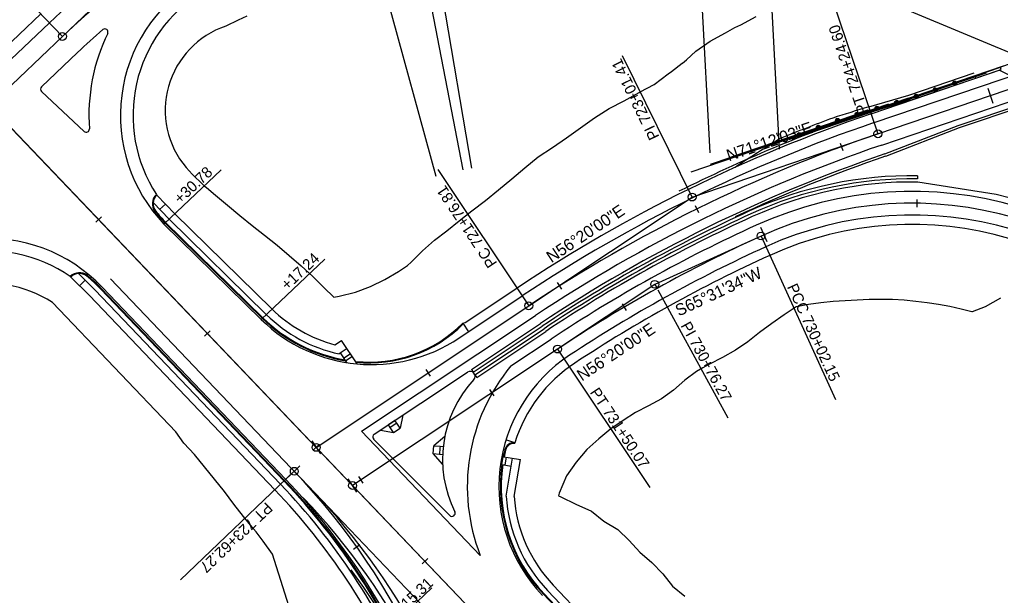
# Model space of a CAD drawing. Extents: x 1300404 to 1323571, y 237813 to 252077.
# Drawn here: x 1310171 to 1310793, y 241355 to 241720 of the extents above; entities that cross this region are included whole.
import ezdxf

# ---------------------------------------------------------------- set-up
doc = ezdxf.new("R2010")
doc.units = 0
for name, color, linetype in [('R_Barrier Wall', 7, 'Continuous'), ('R_Bridge', 7, 'Continuous'), ('R_Const Limits', 7, 'Continuous'), ('R_Curb', 7, 'Continuous'), ('R_Draft', 7, 'Continuous'), ('R_Flooplain', 7, 'Continuous'), ('R_Future', 7, 'Continuous'), ('R_Guardrail', 7, 'Continuous'), ('R_Horz Alg Annot', 7, 'Continuous'), ('R_Horz Alg Annot Leader', 7, 'Continuous'), ('R_Horz Alg Major Ticks', 7, 'Continuous'), ('R_Horz Alg Minor Ticks', 7, 'Continuous'), ('R_Horz Alg Tangents', 7, 'Continuous'), ('R_Horz Alg Tangents Text', 7, 'Continuous'), ('R_Lane Edge', 7, 'Continuous'), ('R_No Plot', 7, 'Continuous'), ('R_Proposed', 7, 'Continuous'), ('R_Shoulder', 7, 'Continuous'), ('R_Sidewalk Edge', 7, 'Continuous')]:
    doc.layers.add(name, color=color, linetype=linetype)

msp = doc.modelspace()

# ---------------------------------------------------------------- linework, layer by layer
at = {"layer": 'R_Barrier Wall'}
for p, q in [((1310740.8, 241621.29), (1310740.77, 241619.29)), ((1310458.67, 241496.57), (1310502.53, 241525.79)), ((1310459.78, 241494.91), (1310503.64, 241524.12)), ((1310459.78, 241494.91), (1310458.67, 241496.57))]:
    msp.add_line(p, q, dxfattribs=at)
for centre, radius, start, end in [((1310737.29, 241372.32), 249, 89.19241, 114.47385), ((1310737.29, 241372.32), 247, 89.19241, 114.47385), ((1311023.32, 240743.92), 939.43, 114.47385, 123.66667), ((1311023.32, 240743.92), 937.43, 114.47385, 123.66667)]:
    msp.add_arc(centre, radius, start, end, dxfattribs=at)
at = {"layer": 'R_Bridge'}
for p, q in [((1311052, 241778.36), (1310793.35, 241690.31)), ((1310777.26, 241684.81), (1310793.35, 241690.31)), ((1310777.77, 241683.31), (1310793.86, 241688.82)), ((1310824.24, 241672.75), (1310792.52, 241688.36)), ((1310793.86, 241688.82), (1310793.35, 241690.31)), ((1310777.77, 241683.31), (1310777.26, 241684.81))]:
    msp.add_line(p, q, dxfattribs=at)
at = {"layer": 'R_Const Limits'}
msp.add_line((1310191.61, 241540.77), (1310269.94, 241458.71), dxfattribs=at)
for points in [[(1310314.9, 241722.64), (1310309.35, 241720.2), (1310301.58, 241716.34)], [(1310584.48, 241687.59), (1310591.41, 241692.73), (1310591.43, 241692.75), (1310594.13, 241695.01), (1310599.9, 241700.51), (1310609.14, 241706.76), (1310618.85, 241711.98), (1310624.67, 241715.54), (1310628.59, 241717.21), (1310638.32, 241722.5)], [(1310370.08, 241544.27), (1310373.6, 241544.72), (1310383.89, 241547.31), (1310393.48, 241550.95), (1310402.48, 241555.48), (1310411.22, 241560.38), (1310416.88, 241564.18), (1310419.22, 241566.42), (1310426.5, 241573.52), (1310434.03, 241580.27), (1310441.96, 241586.4), (1310449.77, 241592.71), (1310457.88, 241598.99), (1310466.44, 241605.52), (1310474.79, 241612.43), (1310483.12, 241619.4), (1310491.51, 241626.35), (1310499.99, 241633.22), (1310509.05, 241639.14), (1310517.95, 241645.38), (1310526.77, 241651.8), (1310535.69, 241658.1), (1310544.88, 241663.94), (1310554.52, 241668.94), (1310564.05, 241674.17), (1310564.71, 241674.57), (1310573.63, 241679.31), (1310582.46, 241686.09), (1310584.48, 241687.59)], [(1310276.4, 241626.48), (1310280.14, 241622.4), (1310287.31, 241615.42), (1310287.9, 241614.9), (1310289.27, 241613.78), (1310295.05, 241608.98), (1310302.77, 241602.52), (1310310.57, 241596.14), (1310318.39, 241589.78), (1310326.25, 241583.46), (1310334.12, 241577.15), (1310341.84, 241570.69), (1310349.39, 241564.08), (1310356.82, 241557.34), (1310363.87, 241550.24), (1310370.08, 241544.27)], [(1310793.35, 241543.52), (1310783.74, 241538.05), (1310775.34, 241534.81), (1310775.3, 241534.82), (1310768.35, 241536.63), (1310761.29, 241538.23), (1310754.15, 241539.61), (1310746.93, 241540.56), (1310739.67, 241541.4), (1310732.34, 241542.17), (1310724.95, 241542.66), (1310717.52, 241542.73), (1310710.03, 241542.64), (1310702.49, 241542.33), (1310694.86, 241541.94), (1310687.16, 241541.37), (1310679.38, 241540.57), (1310671.54, 241539.5), (1310663.69, 241538.06), (1310663.69, 241538.06), (1310655.99, 241533.02), (1310648.19, 241527.46), (1310640.52, 241521.69), (1310632.95, 241515.83), (1310625.11, 241510.58), (1310616.97, 241505.92), (1310608.62, 241501.68), (1310604.51, 241499.3), (1310600.51, 241496.99), (1310592.94, 241491.35), (1310585.75, 241485.13), (1310578.22, 241479.54), (1310570, 241475.1), (1310561.6, 241470.92), (1310553.78, 241465.81), (1310546.04, 241460.59), (1310545.98, 241460.55), (1310538.33, 241454.13), (1310530.82, 241447.37), (1310524.1, 241439.42), (1310517.88, 241430.71), (1310513.23, 241419.66), (1310512.73, 241417.99)], [(1310353.4, 241310.55), (1310353.4, 241310.55), (1310353.4, 241310.55), (1310353.4, 241310.55), (1310331.28, 241380.9), (1310331.28, 241380.9), (1310331.28, 241380.9), (1310331.28, 241380.9), (1310331.28, 241380.9), (1310331.28, 241380.9), (1310325.41, 241389.12), (1310320.8, 241395.02), (1310319.2, 241397.02), (1310312.88, 241404.81), (1310306.59, 241412.63), (1310300.69, 241420.82), (1310294.4, 241428.64), (1310288.08, 241436.43), (1310281.76, 241444.22), (1310274.87, 241451.47), (1310269.94, 241458.71)], [(1310512.73, 241417.99), (1310514.22, 241417.27), (1310523.82, 241412.62), (1310533.74, 241408.26), (1310541.64, 241401.97), (1310550.52, 241396.63), (1310557.77, 241389.72), (1310564.39, 241382.22), (1310571.99, 241375.65), (1310579.02, 241368.53), (1310585.25, 241360.65), (1310592.98, 241354.21)]]:
    msp.add_lwpolyline(points, dxfattribs=at)
for centre, radius, start, end in [((1310319.65, 241662.82), 56.49, 108.65527, 220.03677), ((1310151.28, 241478.79), 73.94, 56.94848, 152.94523)]:
    msp.add_arc(centre, radius, start, end, dxfattribs=at)
at = {"layer": 'R_Curb'}
for p, q in [((1310324.82, 241530.66), (1310263.03, 241591.22)), ((1310325.17, 241531.02), (1310263.38, 241591.57)), ((1310221.96, 241549.52), (1310338.56, 241427.37)), ((1310222.32, 241549.87), (1310338.92, 241427.71)), ((1310503.65, 241355.78), (1310622.61, 241231.16)), ((1310503.29, 241355.44), (1310622.23, 241230.84))]:
    msp.add_line(p, q, dxfattribs=at)
for centre, radius, start, end in [((1310262.92, 241603.57), 8, 132.64931, 217.96091), ((1310262.92, 241603.57), 7.5, 133.28925, 217.96091), ((1310334.67, 241659.55), 99, 217.96123, 223.66667), ((1310334.67, 241659.55), 98.5, 217.96123, 223.66667), ((1310208.6, 241551.72), 8, 50.49362, 135.80556), ((1310208.6, 241551.72), 7.5, 50.49362, 135.80556), ((1310150.71, 241481.51), 98.5, 43.66667, 50.49362), ((1310150.71, 241481.51), 99, 43.66667, 50.49362), ((1310394.12, 241601.36), 99, 225.57582, 260.49906), ((1310394.12, 241601.36), 98.5, 225.57582, 260.22564), ((1310392.66, 241586.67), 83.73, 264.06748, 315.12019), ((1310392.66, 241586.67), 84.23, 264.34826, 315.05129), ((1310484.54, 241445.76), 6, 84.11696, 166.34051), ((1310484.54, 241445.76), 5.5, 85.15463, 166.3405), ((1310574.91, 241423.8), 99, 166.34071, 168.90949), ((1310574.91, 241423.8), 98.5, 166.34071, 168.90215), ((1310574.91, 241423.8), 99, 171.80353, 223.66667), ((1310574.91, 241423.8), 98.5, 171.81087, 223.66667), ((1310032.27, 241135.01), 423.42, 22.2443, 43.66667), ((1310032.27, 241135.01), 423.92, 21.97246, 43.66667)]:
    msp.add_arc(centre, radius, start, end, dxfattribs=at)
at = {"layer": 'R_Draft'}
for centre, start, end in [((1310334.67, 241659.55), 121.63465, 223.66667), ((1310150.71, 241481.51), 43.66667, 147.10039)]:
    msp.add_arc(centre, 100, start, end, dxfattribs=at)
at = {"layer": 'R_Flooplain'}
msp.add_lwpolyline([(1309009.78, 242685.04), (1309044.07, 242596.21), (1309055.9, 242542.38), (1309352.07, 242367.77), (1309503.16, 242292.41), (1309669.46, 242230.8), (1309815.49, 242150.85), (1309936.66, 242057.64), (1310419.39, 241839.75), (1310733.16, 241727.16), (1311043.67, 241597.79), (1311103.17, 241577.86), (1311152.77, 241553.58), (1311178, 241525.7), (1311328.48, 241486.66), (1311553.07, 241380.98), (1311870.34, 241289.99), (1312137.52, 241213.62)], dxfattribs=at)
at = {"layer": 'R_Future'}
msp.add_line((1310228.47, 241555.74), (1310356.22, 241421.9), dxfattribs=at)
for radius, end in [(432.42, 43.66667), (424.92, 43.66667), (418.92, 36.25513)]:
    msp.add_arc((1310043.42, 241123.33), radius, 336.82333, end, dxfattribs=at)
at = {"layer": 'R_Guardrail'}
for p, q in [((1310695.74, 241656.55), (1310784.48, 241686.76)), ((1310795.06, 241690.87), (1310710.74, 241662.17)), ((1310683.4, 241652.3), (1310772.14, 241682.51)), ((1310736.34, 241669.24), (1310777.76, 241683.34)), ((1310765.05, 241679.12), (1310763.06, 241680.05)), ((1310659, 241644.31), (1310747.75, 241674.52)), ((1310671.39, 241648.23), (1310760.13, 241678.44)), ((1310752.71, 241674.86), (1310750.72, 241675.79)), ((1310633.75, 241636.67), (1310722.5, 241666.88)), ((1310646.47, 241640.5), (1310735.21, 241670.71)), ((1310736.34, 241669.24), (1310688.1, 241654.62)), ((1310728.31, 241666.87), (1310726.33, 241667.8)), ((1310740.7, 241670.8), (1310738.71, 241671.73)), ((1310827.89, 241672.29), (1310767.18, 241651.63)), ((1310621.4, 241632.92), (1310710.15, 241663.13)), ((1310715.78, 241663.07), (1310713.79, 241664)), ((1310609.24, 241628.56), (1310697.99, 241658.77)), ((1310690.71, 241655.48), (1310688.73, 241656.41)), ((1310703.06, 241659.24), (1310701.08, 241660.17)), ((1310597.12, 241623.81), (1310685.87, 241654.02)), ((1310678.55, 241651.12), (1310676.57, 241652.05)), ((1310767.18, 241651.63), (1310720.49, 241633.62)), ((1310666.43, 241646.37), (1310664.45, 241647.3))]:
    msp.add_line(p, q, dxfattribs=at)
for points in [[(1310765.39, 241679.51), (1310763.15, 241680.55)], [(1310764.35, 241678.86), (1310763.32, 241679.34)], [(1310765.53, 241679.98), (1310763.42, 241680.97)], [(1310765.49, 241680.55), (1310763.88, 241681.3)], [(1310753.05, 241675.25), (1310750.81, 241676.3)], [(1310752.01, 241674.61), (1310750.98, 241675.09)], [(1310753.19, 241675.73), (1310751.08, 241676.72)], [(1310753.15, 241676.3), (1310751.55, 241677.05)], [(1310728.65, 241667.26), (1310726.41, 241668.31)], [(1310727.61, 241666.61), (1310726.58, 241667.09)], [(1310728.8, 241667.74), (1310726.68, 241668.73)], [(1310728.75, 241668.31), (1310727.15, 241669.06)], [(1310741.04, 241671.19), (1310738.79, 241672.24)], [(1310739.99, 241670.54), (1310738.97, 241671.02)], [(1310741.18, 241671.67), (1310739.07, 241672.65)], [(1310741.14, 241672.23), (1310739.53, 241672.98)], [(1310703.4, 241659.63), (1310701.16, 241660.67)], [(1310703.55, 241660.1), (1310701.43, 241661.09)], [(1310703.5, 241660.67), (1310701.9, 241661.42)], [(1310716.12, 241663.46), (1310713.88, 241664.5)], [(1310715.08, 241662.81), (1310714.05, 241663.29)], [(1310716.26, 241663.93), (1310714.15, 241664.92)], [(1310716.22, 241664.5), (1310714.62, 241665.25)], [(1310691.05, 241655.87), (1310688.81, 241656.92)], [(1310690.01, 241655.23), (1310688.98, 241655.71)], [(1310691.2, 241656.35), (1310689.08, 241657.34)], [(1310691.15, 241656.92), (1310689.55, 241657.67)], [(1310702.36, 241658.98), (1310701.34, 241659.46)], [(1310666.92, 241647.24), (1310664.8, 241648.22)], [(1310666.87, 241647.8), (1310665.27, 241648.55)], [(1310678.89, 241651.51), (1310676.65, 241652.56)], [(1310677.85, 241650.86), (1310676.82, 241651.34)], [(1310679.04, 241651.99), (1310676.92, 241652.98)], [(1310678.99, 241652.56), (1310677.39, 241653.31)], [(1310666.77, 241646.76), (1310664.53, 241647.81)], [(1310665.73, 241646.11), (1310664.7, 241646.59)]]:
    msp.add_lwpolyline(points, dxfattribs=at)
for centre in [(1310764.31, 241680.13), (1310739.96, 241671.81), (1310751.97, 241675.87), (1310727.58, 241667.88), (1310702.33, 241660.25), (1310715.04, 241664.08), (1310689.98, 241656.49), (1310665.7, 241647.38), (1310677.81, 241652.13)]:
    msp.add_circle(centre, 1.25, dxfattribs=at)
for centre, radius, start, end in [((1311023.32, 240743.9), 970.01, 108.79905, 116.57911), ((1311023.32, 240743.92), 970.43, 110.20788, 111.71745), ((1311023.33, 240743.9), 939.85, 108.79713, 115.07369)]:
    msp.add_arc(centre, radius, start, end, dxfattribs=at)
at = {"layer": 'R_Horz Alg Annot'}
for p, q in [((1310262.33, 241590.5), (1310298.54, 241625.06)), ((1310324.12, 241529.95), (1310364.42, 241568.41))]:
    msp.add_line(p, q, dxfattribs=at)
at = {"layer": 'R_Horz Alg Annot Leader'}
msp.add_line((1310418.29, 241346.01), (1310432.36, 241359.45), dxfattribs=at)
for points in [[(1310197.87, 241709.76), (1310171.2, 241737.69)], [(1310687.13, 241731.51), (1310715.59, 241647.91)], [(1310597.64, 241607.76), (1310553.44, 241697.46)], [(1310436.23, 241625.33), (1310493.94, 241538.69)], [(1310641.38, 241583.02), (1310688.62, 241479.23)], [(1310573.92, 241552.31), (1310574.92, 241550.49)], [(1310575.79, 241548.91), (1310620.4, 241467.47)], [(1310512.23, 241511.22), (1310570.82, 241423.27)], [(1310345.07, 241433.58), (1310272.73, 241364.53)]]:
    msp.add_lwpolyline(points, dxfattribs=at)
at = {"layer": 'R_Horz Alg Major Ticks'}
for points in [[(1310785.35, 241676.94), (1310788.57, 241667.47)], [(1310645.37, 241579.33), (1310641.31, 241588.47)], [(1310356.15, 241452.92), (1310361.7, 241444.6)], [(1310356.15, 241452.92), (1310361.7, 241444.6)], [(1310341.45, 241430.13), (1310348.69, 241437.03)], [(1310384.83, 241420.36), (1310379.29, 241428.68)]]:
    msp.add_lwpolyline(points, dxfattribs=at)
at = {"layer": 'R_Horz Alg Minor Ticks'}
for points in [[(1310691.53, 241642.03), (1310693.26, 241637.34)], [(1310740.51, 241601.3), (1310740.58, 241606.3)], [(1310599.47, 241602.43), (1310601.68, 241597.94)], [(1310222.64, 241595.16), (1310219.02, 241591.71)], [(1310512.05, 241553.42), (1310514.72, 241549.19)], [(1310555.91, 241535.68), (1310553.37, 241539.99)], [(1310291.69, 241522.82), (1310288.07, 241519.37)], [(1310428.62, 241498.19), (1310431.39, 241494.02)], [(1310472.06, 241481.46), (1310469.29, 241485.62)], [(1310360.73, 241450.48), (1310357.11, 241447.03)], [(1310388.83, 241426.03), (1310386.06, 241430.19)], [(1310382.64, 241384.15), (1310386.72, 241387.05)], [(1310429.78, 241378.15), (1310426.16, 241374.69)]]:
    msp.add_lwpolyline(points, dxfattribs=at)
at = {"layer": 'R_Horz Alg Tangents'}
for p, q in [((1310197.87, 241709.76), (1310313.6, 241820.22)), ((1310597.64, 241607.76), (1310715.59, 241647.91)), ((1310493.94, 241538.69), (1310597.64, 241607.76)), ((1310641.38, 241583.02), (1310573.92, 241552.31)), ((1310573.92, 241552.31), (1310512.23, 241511.22)), ((1310577.76, 241189.8), (1310345.07, 241433.58))]:
    msp.add_line(p, q, dxfattribs=at)
at = {"layer": 'R_Lane Edge'}
for p, q in [((1310713.17, 241655.01), (1311572.42, 241947.51)), ((1310718.01, 241640.81), (1311577.25, 241933.31)), ((1310165.2, 241695.16), (1310189.58, 241718.44)), ((1310184.6, 241677.73), (1310207.53, 241699.63)), ((1310211.61, 241649.44), (1310184.61, 241674.83)), ((1310257.5, 241609.46), (1310257.78, 241609.03)), ((1310324.12, 241529.95), (1310262.33, 241590.5)), ((1310203.22, 241556.95), (1310202.86, 241557.3)), ((1310223.05, 241550.56), (1310339.64, 241428.4)), ((1310449.55, 241518.14), (1310489.78, 241544.93)), ((1310387.84, 241459.01), (1310498.1, 241532.45)), ((1310452, 241527.58), (1310455.6, 241522.17)), ((1310482.64, 241500.53), (1310508.08, 241517.47)), ((1310395.77, 241457.08), (1310454.97, 241496.51)), ((1310463.13, 241380.14), (1310387.84, 241459.01)), ((1310443.76, 241405.52), (1310395.46, 241454)), ((1310485.15, 241451.73), (1310479.42, 241453.51)), ((1310485, 241451.24), (1310485.15, 241451.73))]:
    msp.add_line(p, q, dxfattribs=at)
for centre, radius, start, end in [((1310496.44, 241396.96), 444.42, 93.06037, 133.66667), ((1310334.67, 241659.55), 100, 121.63465, 223.66667), ((1310496.44, 241396.96), 418.42, 130.71608, 133.66667), ((1310334.67, 241659.55), 120, 154.23405, 184.06474), ((1310224.8, 241712.58), 2, 334.23359, 130.71634), ((1310185.98, 241676.29), 2, 133.66667, 226.76016), ((1311023.32, 240743.92), 962.43, 108.79905, 123.66667), ((1310212.98, 241650.9), 2, 226.76016, 4.06474), ((1311023.32, 240743.92), 947.43, 108.79905, 123.66667), ((1310737.29, 241372.32), 239, 311.16667, 114.47385), ((1310737.29, 241372.32), 224, 311.16667, 114.47385), ((1311023.32, 240743.92), 929.43, 114.47385, 123.66667), ((1310150.71, 241481.51), 100, 43.66667, 147.10039), ((1311023.32, 240743.92), 914.43, 114.47385, 123.40686), ((1310394.12, 241601.36), 100, 225.57582, 303.66667), ((1310574.91, 241423.8), 100, 123.40686, 223.66667), ((1310574.91, 241423.8), 120, 140.25051, 201.33502), ((1310456.7, 241493.92), 3.12, 317.4059, 123.66667), ((1310514.2, 241441.05), 75, 137.40588, 206.29937), ((1310396.88, 241455.41), 2, 123.66667, 224.88819), ((1310514.2, 241441.05), 77, 173.73262, 177.45378), ((1310032.27, 241135.01), 424.92, 327.80537, 43.66667), ((1310445.17, 241406.93), 2, 224.88819, 26.29937)]:
    msp.add_arc(centre, radius, start, end, dxfattribs=at)
at = {"layer": 'R_No Plot'}
for p, q in [((1310609.19, 241635.74), (1310598.52, 241835.45)), ((1310642.2, 241837.79), (1310652.88, 241638.07)), ((1310424.03, 241823.27), (1310457.52, 241626.09)), ((1310452.23, 241625.13), (1310414.19, 241821.48)), ((1310390.21, 241784.27), (1310434.96, 241621.1))]:
    msp.add_line(p, q, dxfattribs=at)
at = {"layer": 'R_Proposed'}
for p, q in [((1310715.59, 241647.91), (1311574.84, 241940.41)), ((1310111.34, 241627.16), (1310197.87, 241709.76)), ((1310111.34, 241627.16), (1310197.87, 241709.76)), ((1310111.34, 241627.16), (1310197.87, 241709.76)), ((1310151.78, 241665.77), (1310197.87, 241709.76)), ((1310151.78, 241665.77), (1311952.58, 239779.15)), ((1310165.59, 241651.3), (1311952.63, 239779.09)), ((1310165.59, 241651.3), (1311952.63, 239779.09)), ((1310358.92, 241448.76), (1310493.94, 241538.69)), ((1310512.23, 241511.22), (1310382.06, 241424.52))]:
    msp.add_line(p, q, dxfattribs=at)
for centre in [(1310197.87, 241709.76), (1310715.59, 241647.91), (1310597.64, 241607.76), (1310641.38, 241583.02), (1310573.92, 241552.31), (1310493.94, 241538.69), (1310512.23, 241511.22), (1310358.92, 241448.76), (1310345.07, 241433.58), (1310382.06, 241424.52)]:
    msp.add_circle(centre, 2.5, dxfattribs=at)
for centre, radius, start, end in [((1310496.44, 241396.96), 432.42, 93.06037, 133.66667), ((1311023.32, 240743.92), 954.93, 108.79906, 123.66667), ((1310737.29, 241372.32), 231.5, 311.16667, 114.47385), ((1311023.32, 240743.92), 921.93, 114.47385, 123.66667), ((1310032.27, 241135.01), 432.42, 327.80537, 43.66667), ((1310032.27, 241135.01), 432.42, 327.80537, 43.66667)]:
    msp.add_arc(centre, radius, start, end, dxfattribs=at)
at = {"layer": 'R_Shoulder'}
for p, q in [((1310766.63, 241653.14), (1311578.54, 241929.52)), ((1310137.98, 241680.24), (1310184.06, 241724.22)), ((1310711.24, 241660.69), (1310792.52, 241688.36)), ((1310735.22, 241672.55), (1310776.63, 241686.65)), ((1310709.8, 241665.01), (1310735.22, 241672.55)), ((1310719.94, 241635.13), (1310766.63, 241653.14)), ((1310790.63, 241609.39), (1310740.89, 241617.29)), ((1310453.53, 241527.99), (1310486.46, 241549.93)), ((1310452, 241527.58), (1310453.53, 241527.99)), ((1310457.56, 241498.24), (1310501.42, 241527.45)), ((1310460.89, 241493.24), (1310504.75, 241522.46)), ((1310457.56, 241498.24), (1310458.67, 241496.57)), ((1310459.78, 241494.91), (1310460.89, 241493.24))]:
    msp.add_line(p, q, dxfattribs=at)
for centre, radius, start, end in [((1310334.67, 241659.55), 92, 121.63465, 212.98944), ((1311023.32, 240743.92), 968.43, 108.79905, 123.66667), ((1310986.89, 240731.33), 973.93, 106.52925, 107.93807), ((1311023.32, 240743.92), 973.93, 110.20788, 112.30788), ((1311169.5, 240806.87), 984.13, 121.61376, 123.59375), ((1311023.32, 240743.92), 941.43, 108.79905, 123.66667), ((1310737.29, 241372.32), 245, 89.15679, 114.47385), ((1310737.29, 241372.32), 243, 311.16667, 77.31825), ((1311023.32, 240743.92), 935.43, 114.47385, 123.66667), ((1310737.29, 241372.32), 218, 311.16667, 114.47385), ((1310150.71, 241481.51), 92, 55.46543, 147.18278), ((1311023.32, 240743.92), 908.43, 114.47385, 123.40686), ((1310574.91, 241423.8), 94, 123.40686, 162.71475)]:
    msp.add_arc(centre, radius, start, end, dxfattribs=at)
at = {"layer": 'R_Sidewalk Edge'}
for p, q in [((1310257.78, 241609.03), (1310269.21, 241597.06)), ((1310255.45, 241604.23), (1310265.59, 241593.61)), ((1310263.21, 241603.34), (1310259.6, 241599.89)), ((1310327.27, 241533.16), (1310265.59, 241593.61)), ((1310330.77, 241536.73), (1310269.21, 241597.07)), ((1310214.95, 241545.28), (1310203.22, 241556.95)), ((1310218.53, 241548.78), (1310208.05, 241559.2)), ((1310208.77, 241551.43), (1310212.3, 241554.97)), ((1310218.53, 241548.78), (1310336.39, 241425.3)), ((1310214.95, 241545.28), (1310332.77, 241421.84)), ((1310370.85, 241513.91), (1310375.11, 241516.75)), ((1310378.61, 241511.49), (1310373.54, 241508.11)), ((1310385.08, 241501.77), (1310375.11, 241516.75)), ((1310378.53, 241502.59), (1310374.45, 241508.71)), ((1310380.83, 241508.16), (1310376.67, 241505.39)), ((1310381.94, 241506.49), (1310377.78, 241503.72)), ((1310413.98, 241469.21), (1310412.31, 241460.89)), ((1310408.99, 241465.88), (1310404.83, 241463.11)), ((1310405.93, 241461.45), (1310404.83, 241463.11)), ((1310410.1, 241464.22), (1310405.93, 241461.45)), ((1310408.15, 241458.12), (1310405.93, 241461.45)), ((1310410.1, 241464.22), (1310408.99, 241465.88)), ((1310412.31, 241460.89), (1310410.1, 241464.22)), ((1310408.15, 241458.12), (1310412.31, 241460.89)), ((1310440.66, 241455.74), (1310433.68, 241449.76)), ((1310433.29, 241444.77), (1310433.68, 241449.76)), ((1310433.68, 241449.76), (1310437.66, 241449.45)), ((1310437.66, 241449.45), (1310439.66, 241449.3)), ((1310439.27, 241437.79), (1310433.29, 241444.77)), ((1310433.29, 241444.77), (1310437.28, 241444.47)), ((1310437.28, 241444.47), (1310439.27, 241444.31)), ((1310476.77, 241443.01), (1310488.6, 241441)), ((1310476.92, 241437.91), (1310477.76, 241442.84)), ((1310475.93, 241438.08), (1310482.83, 241436.9)), ((1310478.89, 241437.57), (1310479.73, 241442.5)), ((1310479.59, 241417.83), (1310483.67, 241441.83)), ((1310484.62, 241417.58), (1310488.6, 241441)), ((1310505.82, 241357.86), (1310624.89, 241233.11)), ((1310509.44, 241361.31), (1310628.7, 241236.36))]:
    msp.add_line(p, q, dxfattribs=at)
msp.add_lwpolyline([(1310399.83, 241459.79), (1310408.15, 241458.12)], dxfattribs=at)
for centre, radius, start, end in [((1310394.12, 241601.36), 90.5, 225.57582, 255.09942), ((1310394.12, 241601.36), 95.5, 225.57582, 257.55528), ((1310032.27, 241135.01), 420.42, 23.29162, 43.66667), ((1310032.27, 241135.01), 415.42, 23.38359, 43.66667), ((1310574.91, 241423.8), 95.5, 183.57845, 223.66667), ((1310574.91, 241423.8), 90.5, 183.94046, 223.66667)]:
    msp.add_arc(centre, radius, start, end, dxfattribs=at)

# ---------------------------------------------------------------- texts
at = {"layer": 'R_Horz Alg Annot'}
for s, rotation, p in [('PT 724+24.60', 108.79906, (1310709.74, 241661.95)), ('PI 723+01.41', 116.23286, (1310577.06, 241646.14)), ('+30.78', 43.07689, (1310272.69, 241602.96)), ('PC 721+76.81', 123.66667, (1310474.11, 241565.76)), ('+17.24', 43.07689, (1310340.65, 241548.18)), ('PCC 730+02.15', 294.47385, (1310657.74, 241550.79)), ('PI 730+76.27', 298.71356, (1310590.17, 241526.16)), ('PT 731+50.07', 303.66667, (1310532.44, 241483.71)), ('PT 723+62.27', 223.66667, (1310327.17, 241414.42)), ('+15.31', 43.07689, (1310412.7, 241341.99))]:
    msp.add_text(s, height=7, rotation=rotation, dxfattribs=at).set_placement(p)
at = {"layer": 'R_Horz Alg Tangents Text'}
for s, rotation, p in [('N71%%d12\'03"E', 18.79906, (1310620.97, 241630.39)), ('N56%%d20\'00"E', 33.66667, (1310508.32, 241565.71)), ('S65%%d31\'34"W', 25.04667, (1310589.16, 241531.81)), ('N56%%d20\'00"E', 33.66667, (1310527.66, 241490.56))]:
    msp.add_text(s, height=7.5, rotation=rotation, dxfattribs=at).set_placement(p)

doc.saveas('drawing.dxf')
